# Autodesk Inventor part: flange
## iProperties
Shininess: 25.0
PropertySet Name: _Private Model Information
Created: 2001-04
Part Number: flange
Document SubType Name: Modeling
Designer: JM30159
Material: Stainless Steel, Austenitic
Description: Flange,Steel, Socket,300# ANSI, 1/2"
Control State: 0
Master: False
Checked Out: False
PropertySet Name: Design Tracking Control
Density: 8.03
Volumn: 525.3803307037855
Area: 853.9032187369518
PropertySet Name: Model Information
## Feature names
1. Slip on weld [Revolution]
2. Socket [Revolution]
3. Weld neck [Revolution]
4. Lap joint [Revolution]
5. Blind [Revolution]
6. Hole3
7. Circular Pattern3
